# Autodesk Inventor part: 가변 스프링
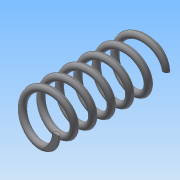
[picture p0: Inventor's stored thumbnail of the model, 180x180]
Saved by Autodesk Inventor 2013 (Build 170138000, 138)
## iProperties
Created: 2015-05
Part Number: 가변 스프링
Material: 일반
Document SubType Name: Modeling
Designer: Administrator
Density: 1 g/cm^3
Author: Administrator
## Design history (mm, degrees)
sketch "스케치1"
  geometry: L1 (0, 0)-(0, 42); L2 (0, 42)-(8, 42); L3 (0, 0)-(8, 0); C1 r 1.25 at (8, 0)
  constraints: 6 end point, 1 centre point, 1 coincident, 1 parallel, 1 perpendicular, 1 vertical
  dimensions: "d0" = 42 distance of L1.start L1.end (derived); "d1" = 8 distance of L1.end L2.end; "d2" = 8 distance of L1.start L3.end; "d3" = 2.5 diameter of C1
feature "코일1" sketch "스케치1" pitch "d4" = 10; turns "d6" = 6; dims "d5" = 42 (= d0), "d7" = 0, angle "d8" = 90 deg, angle "d9" = 90 deg, "d10" = 0, "d11" = 0
sketch "스케치2"
  geometry: L1 (42, 16.451)-(0, 16.451); L2 (0, 16.451)-(0, -16.593); L3 (0, -16.593)-(42, -16.593); L4 (42, -16.593)-(42, 16.451); 1 further point
  constraints: 8 end point, 2 parallel, 1 horizontal, 1 perpendicular, 1 point on line
  dimensions: "d12" = 42 distance of L1.start L1.end (derived); "d14" = 16.45074 distance of point (0, 0) L1.end; "d15" = 16.59256 distance from line of L3 point (0, 0)
extrude "돌출1" sketch "스케치2" stored distance "d16" = 10; taper "d17" = 0 deg
node "솔리드1"
